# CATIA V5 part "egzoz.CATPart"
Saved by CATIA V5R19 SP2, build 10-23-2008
Part number: egzoz
Bounding box of the stored display mesh (mm): x -1324.065 to -1151, y -387.158 to 387.158, z 494.541 to 578.438
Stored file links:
  C:\BEHROOZ\catia learning\tarh haye mashin\hb\egzoz.CATPart
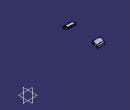
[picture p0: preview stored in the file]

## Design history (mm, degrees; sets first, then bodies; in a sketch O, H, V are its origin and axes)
Body1 (main body)
  Plane1: stored without definition
  DatumSurface1
  Sketch1 on Plane1, origin (-1447, 0, 0), H (0, 1, 0), V (0, 0, 1)
    line L1 (386.5374, 507.3259) -> (376.6723, 533.1573)
    line L2 (253.7771, 567.8954) -> (260.9404, 549.1383)
    frozenspline C1
    frozenspline C2
    arc A1 centre (341.9121, 519.9033) radius 37.2014 from (376.6723, 533.1573) to (355.4701, 554.5461) ccw
    arc A2 centre (261.0401, 570.6693) radius 7.7747 from (262.252, 578.349) to (253.7771, 567.8954) ccw
    arc A3 centre (297.9996, 563.2872) radius 39.6683 from (287.9739, 524.9068) to (260.9404, 549.1383) cw
    arc A4 centre (377.7358, 503.9625) radius 9.4223 from (373.8494, 495.3791) to (386.5374, 507.3259) ccw
    line L3 (366.5256, 516.9572) -> (359.6201, 535.0392)
    line L4 (273.5934, 559.3558) -> (278.6077, 546.2259)
    frozenspline C3
    frozenspline C4
    arc A5 centre (335.2879, 525.7614) radius 26.041 from (359.6201, 535.0392) to (344.7785, 550.0113) ccw
    arc A6 centre (278.6775, 561.2976) radius 5.4423 from (279.5258, 566.6734) to (273.5934, 559.3558) ccw
    arc A7 centre (304.5491, 556.1301) radius 27.7678 from (297.5311, 529.2638) to (278.6077, 546.2259) cw
    arc A8 centre (360.3645, 514.6028) radius 6.5956 from (357.644, 508.5944) to (366.5256, 516.9572) ccw
    line L5 (-386.5374, 507.3259) -> (-376.6723, 533.1573)
    line L6 (-253.7771, 567.8954) -> (-260.9404, 549.1383)
    frozenspline C5
    frozenspline C6
    arc A9 centre (-341.9121, 519.9033) radius 37.2014 from (-376.6723, 533.1573) to (-355.4701, 554.5461) cw
    arc A10 centre (-261.0401, 570.6693) radius 7.7747 from (-262.252, 578.349) to (-253.7771, 567.8954) cw
    arc A11 centre (-297.9996, 563.2872) radius 39.6683 from (-287.9739, 524.9068) to (-260.9404, 549.1383) ccw
    arc A12 centre (-377.7358, 503.9625) radius 9.4223 from (-373.8494, 495.3791) to (-386.5374, 507.3259) cw
    line L7 (-366.5256, 516.9572) -> (-359.6201, 535.0392)
    line L8 (-273.5934, 559.3558) -> (-278.6077, 546.2259)
    frozenspline C7
    frozenspline C8
    arc A13 centre (-335.2879, 525.7614) radius 26.041 from (-359.6201, 535.0392) to (-344.7785, 550.0113) cw
    arc A14 centre (-278.6775, 561.2976) radius 5.4423 from (-279.5258, 566.6734) to (-273.5934, 559.3558) cw
    arc A15 centre (-304.5491, 556.1301) radius 27.7678 from (-297.5311, 529.2638) to (-278.6077, 546.2259) ccw
    arc A16 centre (-360.3645, 514.6028) radius 6.5956 from (-357.644, 508.5944) to (-366.5256, 516.9572) cw
  DatumSurface2 to DatumSurface4
  Join1: Elements (DatumSurface2; DatumSurface3; DatumSurface4)
  Pad1: profile Sketch1, direction (1, 0, 0), up to Join1, offset 9, opposite side length -296
  Fillet1: radius 2, on face of Pad1 (x2)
